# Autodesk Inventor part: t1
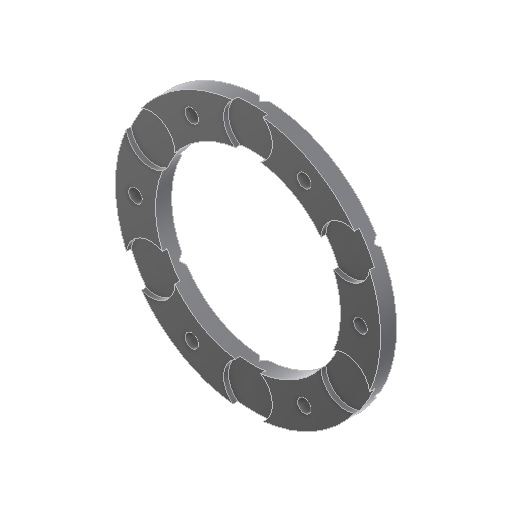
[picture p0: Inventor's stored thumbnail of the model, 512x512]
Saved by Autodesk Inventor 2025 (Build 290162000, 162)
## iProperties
Created: 2025-01
Part Number: t1
Material: Thermoplastic Resin
Document SubType Name: Modeling
Designer: dansp
Density: 1.28 g/cm^3
Appearance: Smooth - Black
Mass: 15.0278 g
Surface Area: 81.5062 cm^2
Volume: 11.7404 cm^3
Author: dansp
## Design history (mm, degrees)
sketch "Sketch1"
  geometry: L1 (0, 57.75)-(0, -57.75) reference; L2 (-57.75, 0)-(57.75, 0) reference; C1 r 41.25 at (0, 0); C2 r 28.75 at (0, 0); 1 further point
  constraints: 2 centre point, 2 coincident
  dimensions: "d0" = 82.5 diameter of C1; "d1" = 12.5 radial gap between concentric circles of C1 C2
extrude "Extrusion1" new body sketch "Sketch1" distance "d2" = 5; taper "d3" = 0 deg
sketch "Sketch3" dims "d41" = 70 (= 0.5 x d40 + 0.5 x d39)
  geometry: C1 r 41.25 at (0, 0) reference; C2 r 28.75 at (0, 0) reference; C3 r 7.6 at (0, 35); 1 further point
  constraints: 2 vertical alignment, 1 centre point, 1 coincident, 2 other
  dimensions: "d39" = 82.5 diameter of C1 (derived); "d40" = 57.5 diameter of C2 (derived); "d42" = 15.2 diameter of C3
extrude "Extrusion3" cut sketch "Sketch3" distance "d16" = 1.5; taper "d17" = 0 deg
pattern_circular "Circular Pattern3" dims angle "d19" = 360 deg
sketch "Sketch5"
  geometry: L1 (-40.25, 0)-(40.25, 0) reference; L2 (0, -0.3)-(0, 1.8) reference; L3 (1.5, 0)-(0, 1.5); L4 (0, 1.5)-(-1.5, 0); L5 (-28.75, 0)-(28.75, 0) reference; 2 further points
  constraints: 4 end point, 3 point on line, 1 other
  dimensions: "d29" = 90 deg angle of L4 L3; "d30" = 1.5 distance from line of L3.end L1
extrude "Extrusion5" cut sketch "Sketch5" extent not by distance; stored distance "d31" = 0; taper "d32" = 0 deg
pattern_circular "Circular Pattern5" dims angle "d34" = 360 deg
sketch "Sketch8"
  geometry: L1 (-57.75, 0)-(57.75, 0) reference; L2 (0, -57.75)-(0, 57.75) reference; C1 r 2.1 at (35, 0); C2 r 2.1 at (-35, 0); A1 r 28.75 centre (0, 0) between (3.91, 28.483) and (-3.91, 28.483) reference; A2 r 7.6 centre (0, 35) between (-4.687, 40.983) and (-3.91, 28.483) reference; A3 r 41.25 centre (0, 0) between (4.687, 40.983) and (-4.687, 40.983) reference; A4 r 7.6 centre (0, 35) between (3.91, 28.483) and (4.687, 40.983) reference; A5 r 35 centre (0, 0) between (0, 35) and (35, 0); 1 further point
  constraints: 3 centre point, 2 point on circle, 1 coincident, 1 point on line, 1 symmetric about line, 1 other
  dimensions: "d44" = 4.2 diameter of C1
extrude "Extrusion6" cut sketch "Sketch8" extent not by distance; stored distance "d45" = 0; taper "d46" = 0 deg
pattern_circular "Circular Pattern7" dims angle "d51" = 360 deg
body "Solid1"
node "Projected Loop2"
node "Projected Loop6"
